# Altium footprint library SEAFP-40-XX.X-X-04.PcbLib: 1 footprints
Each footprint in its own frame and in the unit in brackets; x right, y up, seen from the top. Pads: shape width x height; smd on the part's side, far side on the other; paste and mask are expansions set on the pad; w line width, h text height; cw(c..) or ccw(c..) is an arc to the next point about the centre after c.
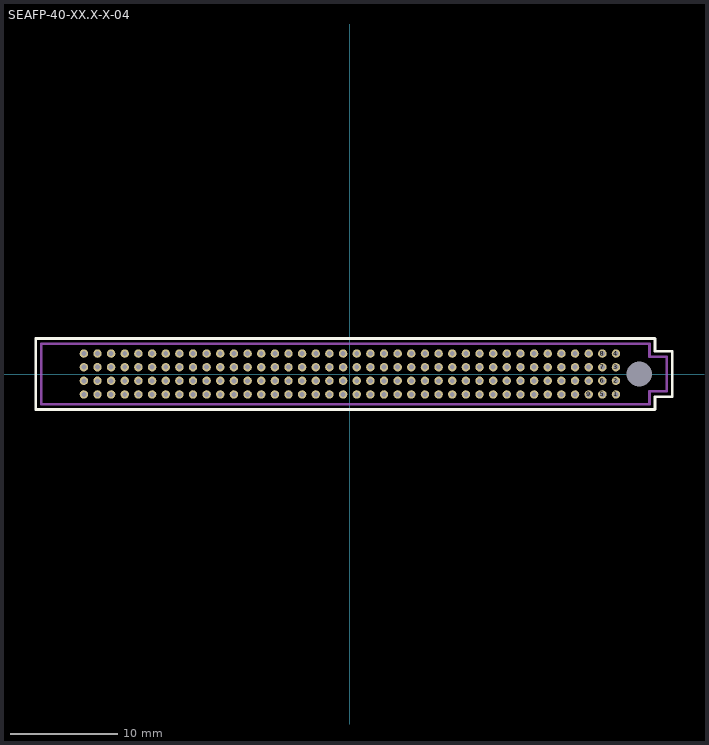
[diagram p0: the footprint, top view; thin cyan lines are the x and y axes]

## SEAFP-40-XX.X-X-04 [mil]
pads (161):
  round 31 hole 18 mask+3: 1(975,-75) 2(975,-25) 3(975,25) 4(975,75) 5(925,-75) 6(925,-25) 7(925,25) 8(925,75) 9(875,-75) 10(875,-25) 11(875,25) 12(875,75) 13(825,-75) 14(825,-25) 15(825,25) 16(825,75) 17(775,-75) 18(775,-25) 19(775,25) 20(775,75) 21(725,-75) 22(725,-25) 23(725,25) 24(725,75) 25(675,-75) 26(675,-25) 27(675,25) 28(675,75) 29(625,-75) 30(625,-25) 31(625,25) 32(625,75) 33(575,-75) 34(575,-25) 35(575,25) 36(575,75) 37(525,-75) 38(525,-25) 39(525,25) 40(525,75) 41(475,-75) 42(475,-25) 43(475,25) 44(475,75) 45(425,-75) 46(425,-25) 47(425,25) 48(425,75) 49(375,-75) 50(375,-25) 51(375,25) 52(375,75) 53(325,-75) 54(325,-25) 55(325,25) 56(325,75) 57(275,-75) 58(275,-25) 59(275,25) 60(275,75) 61(225,-75) 62(225,-25) 63(225,25) 64(225,75) 65(175,-75) 66(175,-25) 67(175,25) 68(175,75) 69(125,-75) 70(125,-25) 71(125,25) 72(125,75) 73(75,-75) 74(75,-25) 75(75,25) 76(75,75) 77(25,-75) 78(25,-25) 79(25,25) 80(25,75) 81(-25,-75) 82(-25,-25) 83(-25,25) 84(-25,75) 85(-75,-75) 86(-75,-25) 87(-75,25) 88(-75,75) 89(-125,-75) 90(-125,-25) 91(-125,25) 92(-125,75) 93(-175,-75) 94(-175,-25) 95(-175,25) 96(-175,75) 97(-225,-75) 98(-225,-25) 99(-225,25) 100(-225,75) 101(-275,-75) 102(-275,-25) 103(-275,25) 104(-275,75) 105(-325,-75) 106(-325,-25) 107(-325,25) 108(-325,75) 109(-375,-75) 110(-375,-25) 111(-375,25) 112(-375,75) 113(-425,-75) 114(-425,-25) 115(-425,25) 116(-425,75) 117(-475,-75) 118(-475,-25) 119(-475,25) 120(-475,75) 121(-525,-75) 122(-525,-25) 123(-525,25) 124(-525,75) 125(-575,-75) 126(-575,-25) 127(-575,25) 128(-575,75) 129(-625,-75) 130(-625,-25) 131(-625,25) 132(-625,75) 133(-675,-75) 134(-675,-25) 135(-675,25) 136(-675,75) 137(-725,-75) 138(-725,-25) 139(-725,25) 140(-725,75) 141(-775,-75) 142(-775,-25) 143(-775,25) 144(-775,75) 145(-825,-75) 146(-825,-25) 147(-825,25) 148(-825,75) 149(-875,-75) 150(-875,-25) 151(-875,25) 152(-875,75) 153(-925,-75) 154(-925,-25) 155(-925,25) 156(-925,75) 157(-975,-75) 158(-975,-25) 159(-975,25) 160(-975,75)
  round 0 hole 93 unplated: 161(1060,0)
Top Overlay:
  lines w10: -1151,-130.5 1118,-130.5 1118,-83 1181,-83 1181,83 1118,83 1118,130.5 -1151,130.5 -1151,-130.5
Mechanical 1:
  lines w10: -1131,-110.5 1098,-110.5 1098,-63 1161,-63 1161,63 1098,63 1098,110.5 -1131,110.5 -1131,-110.5
  text "J1" at -17.57,-18 h30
